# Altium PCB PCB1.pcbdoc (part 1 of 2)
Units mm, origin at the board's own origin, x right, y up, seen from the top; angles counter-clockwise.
Board outline 53.72 x 80.14 mm, 2 copper layers (Top Layer, Bottom Layer); 37 components, 55 nets, 218 pads, 259 vias.
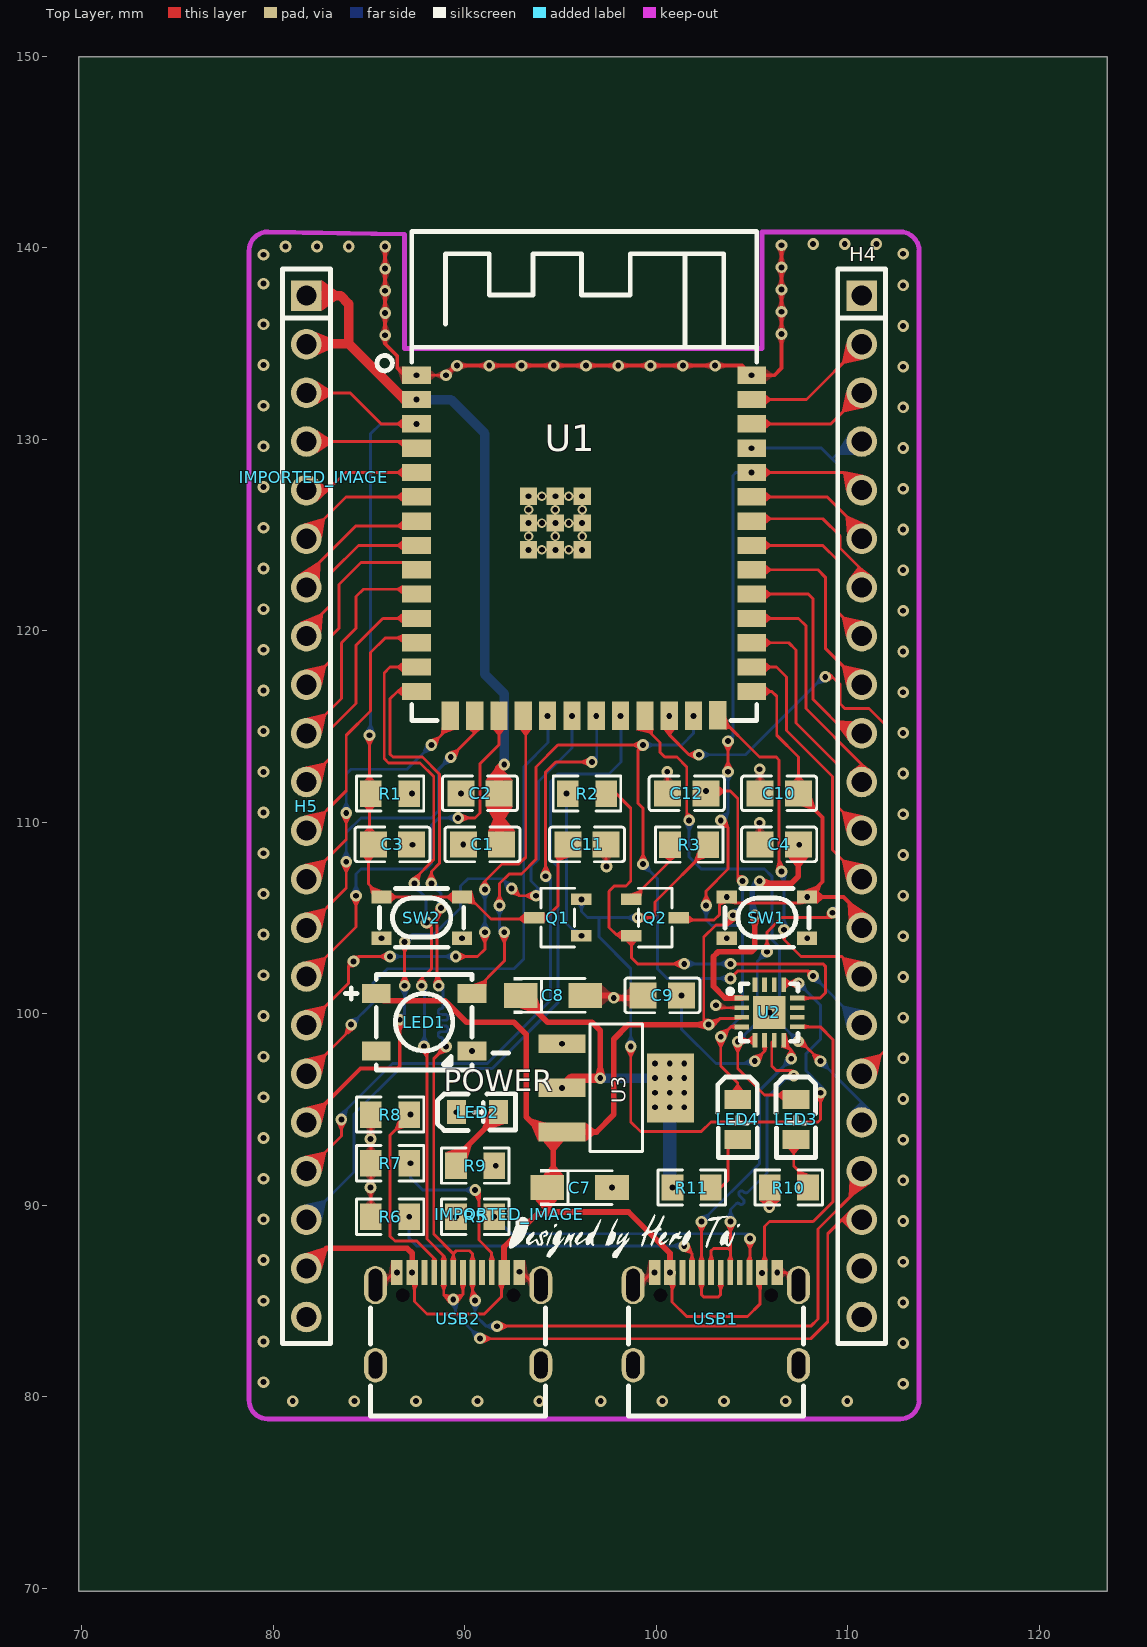
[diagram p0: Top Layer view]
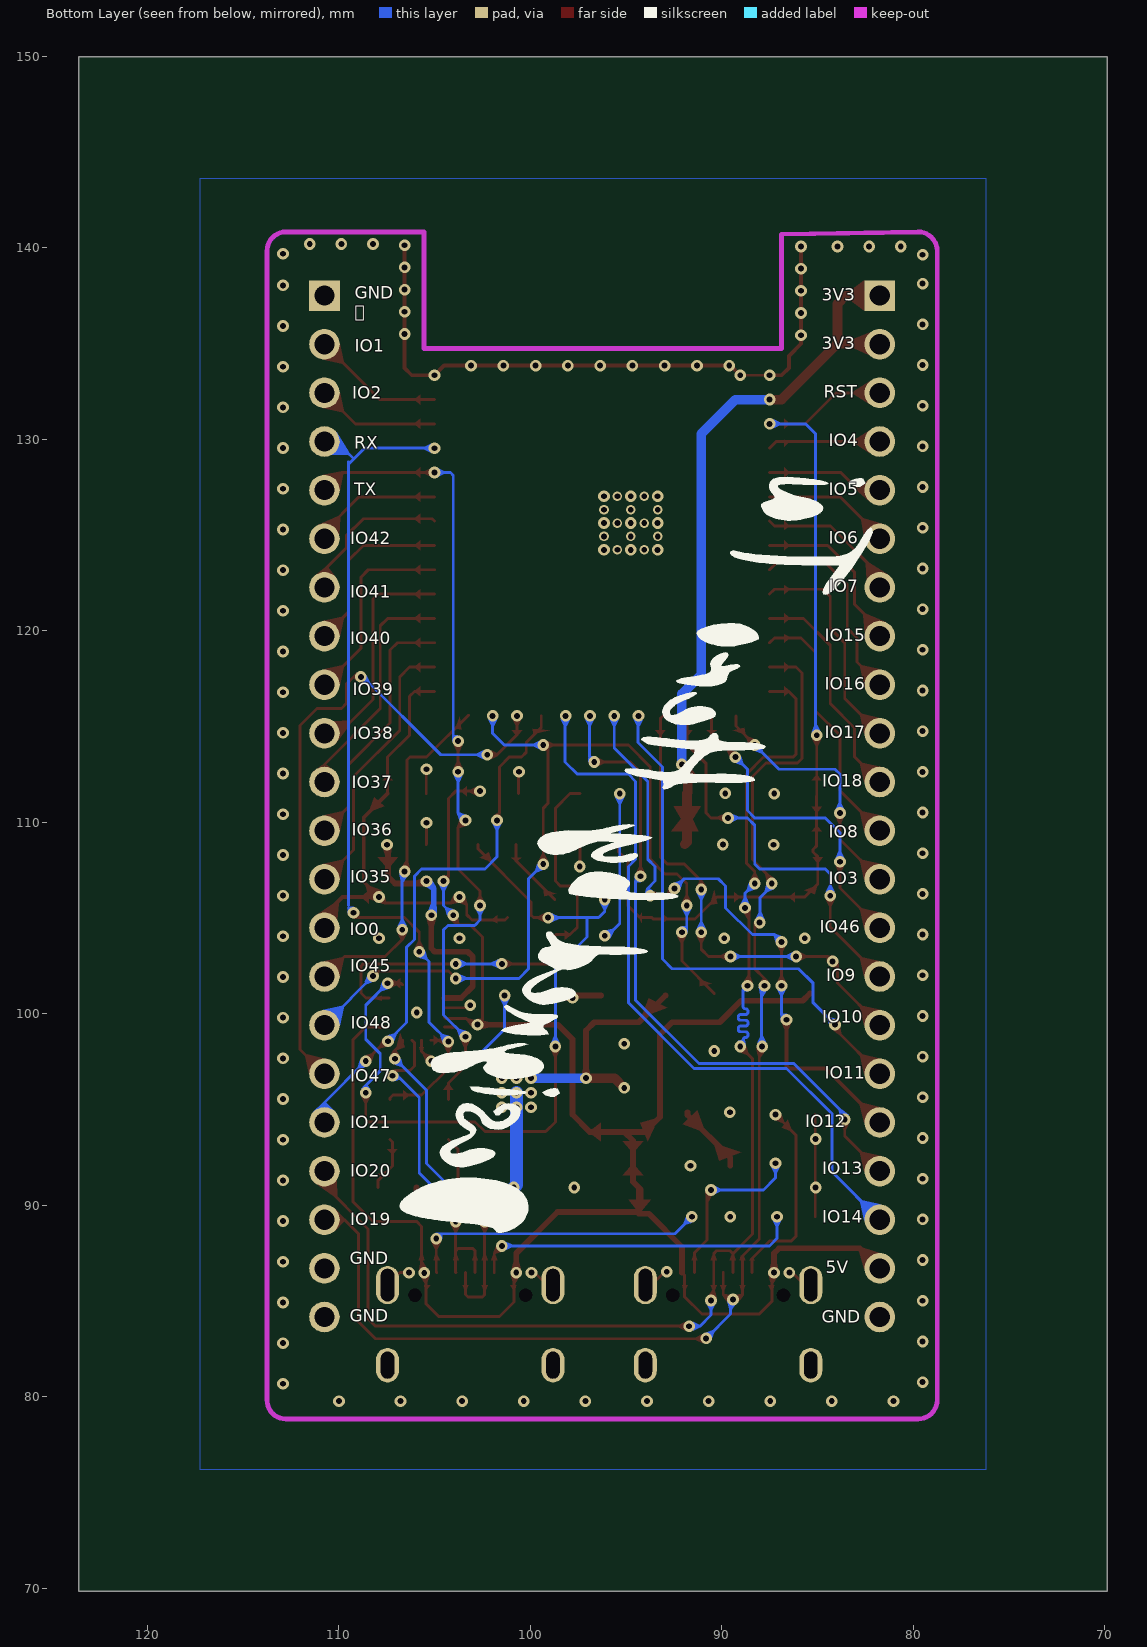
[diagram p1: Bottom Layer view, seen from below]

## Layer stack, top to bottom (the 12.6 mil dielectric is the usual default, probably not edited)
Top Layer: signal copper (thickness not stored)
Dielectric: dielectric 0.32, FR-4, Dk 4.8
Bottom Layer: signal copper (thickness not stored)

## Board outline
123.571,69.85 69.85,69.85 69.85,149.987 123.571,149.987

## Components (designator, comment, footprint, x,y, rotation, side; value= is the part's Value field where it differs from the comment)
C1 "0805B104K500NT" C0805 90.932,108.852 r0 top
C2 "CL21A106KOQNNNE" C0805 90.805,111.519 r0 top
C3 "CL21B105KBFNNNE" C0805 86.233,108.852 r180 top
C4 "CL21B105KBFNNNE" C0805 106.426,108.852 r180 top
C7 "TAJA106K016RNJ" CAP-SMD_L3.2-W1.6-RD-C7171 96.012,90.932 r0 top
C8 "TAJA106K016RNJ" CAP-SMD_L3.2-W1.6-RD-C7171 94.615,100.965 r0 top
C9 "0805B104K500NT" C0805 100.33,100.965 r0 top
C10 "0805B104K500NT" C0805 106.426,111.519 r0 top
C11 "0805B104K500NT" C0805 96.393,108.852 r180 top
C12 "CL21B105KBFNNNE" C0805 101.6,111.519 r0 top
H4 "X6511WV-22H-C30D60" HDR-TH_22P-P2.54-V-M 110.74,110.843 r270 top
H5 "X6511WV-22H-C30D60" HDR-TH_22P-P2.54-V-M 81.74,110.843 r270 top
IMPORTED_IMAGE "IMPORTED_IMAGE" IMPORTED_IMAGE 92.328,89.535 r0 top
IMPORTED_IMAGE "IMPORTED_IMAGE" IMPORTED_IMAGE 82.115,128.021 r0 top
LED1 "XL-5050RGBC-WS2812B" LED-SMD_4P-L5.0-W5.0-BL_XL-5050RGBC 87.884,99.568 r270 top
LED2 "NCD0805R1" LED0805-RD_RED 90.678,94.869 r0 top
LED3 "SZYY0805B" LED0805-R-RD_BLUE 107.315,94.488 r270 top
LED4 "SZYY0805B" LED0805-R-RD_BLUE 104.267,94.488 r270 top
Q1 "SS8050-G_C164886" SOT-23-3_L2.9-W1.6-P1.90-LS2.8-BR 94.869,105.029 r0 top
Q2 "SS8050-G_C164886" SOT-23-3_L2.9-W1.6-P1.90-LS2.8-BR 99.949,105.029 r180 top
R1 "0805W8F1002T5E_C17414" R0805 86.106,111.506 r0 top
R2 "0805W8F1002T5E_C17414" R0805 96.393,111.506 r0 top
R3 "0805W8F1002T5E_C17414" R0805 101.727,108.839 r0 top
R5 "0805W8F5101T5E" R0805 90.551,89.408 r0 top
R6 "0805W8F5101T5E" R0805 86.106,89.408 r0 top
R7 "0805W8F5101T5E" R0805 86.106,92.202 r0 top
R8 "0805W8F5101T5E" R0805 86.106,94.742 r0 top
R9 "RC0805FR-071KL" R0805 90.551,92.075 r180 top
R10 "RC0805FR-071KL" R0805 106.934,90.932 r180 top
R11 "RC0805FR-071KL" R0805 101.854,90.932 r180 top
SW1 "SKRPACE010" KEY-SMD_4P-L4.2-W3.2-P2.20-LS4.6 105.791,105.029 r0 top
SW2 "SKRPACE010" KEY-SMD_4P-L4.2-W3.2-P2.20-LS4.6 87.757,105.029 r0 top
U1 "ESP32-S3-WROOM-1-N16R8" WIRELM-SMD_ESP32-S3-WROOM-1 96.24,124.46 r0 top
U2 "CH343P" TQFN-16_L3.0-W3.0-P0.50-BL-EP1.7 105.918,100.076 r270 top
U3 "AMS1117-3.3_C347222" SOT-223-4_L6.5-W3.5-P2.30-LS7.0-BR 97.917,96.139 r180 top
USB1 "KH-TYPE-C-16P" USB-C-SMD_KH-TYPE-C-16P 103.124,84.074 r0 top
USB2 "KH-TYPE-C-16P" USB-C-SMD_KH-TYPE-C-16P 89.662,84.074 r0 top

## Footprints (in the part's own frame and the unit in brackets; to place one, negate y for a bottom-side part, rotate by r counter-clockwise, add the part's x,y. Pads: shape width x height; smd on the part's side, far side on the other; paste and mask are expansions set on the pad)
C0805 [mm]
  rect 1.41x1.35 smd paste-100 mask+0.051: 1(-1,0) 2(1,0)
  silkscreen extent -1.96,-0.9 1.96,0.9
CAP-SMD_L3.2-W1.6-RD-C7171 [mm]
  rect 1.758x1.296 smd paste+0 mask+0.051: 1(-1.686,0) 2(1.686,0)
  silkscreen extent -2.06,-0.95 1.68,0.95
HDR-TH_22P-P2.54-V-M [mm]
  rect 1.6x1.6 hole 1.05 paste+0 mask+0.051: 1(-26.67,0)
  round 1.6 hole 1.05 paste+0 mask+0.051: 2(-24.13,0) 3(-21.59,0) 4(-19.05,0) 5(-16.51,0) 6(-13.97,0) 7(-11.43,0) 8(-8.89,0) 9(-6.35,0) 10(-3.81,0) 11(-1.27,0) 12(1.27,0) 13(3.81,0) 14(6.35,0) 15(8.89,0) 16(11.43,0) 17(13.97,0) 18(16.51,0) 19(19.05,0) 20(21.59,0) 21(24.13,0) 22(26.67,0)
  silkscreen extent -28.06,-1.25 28.06,1.25
IMPORTED_IMAGE [mm]
  silkscreen extent 0,-2.29 12.07,0
KEY-SMD_4P-L4.2-W3.2-P2.20-LS4.6 [mm]
  rect 1.05x0.7 smd paste+0 mask+0.051: 1(-2.1,1.075) 2(2.1,1.075) 3(-2.1,-1.075) 4(2.1,-1.075)
  silkscreen extent -2.2,-1.55 2.2,1.52
LED0805-R-RD_BLUE [mm]
  rect 1x1.4 smd paste+0 mask+0.051: 1(1.05,0) 2(-1.05,0)
  silkscreen extent -2.22,-1.04 1.99,1.01
LED0805-RD_RED [mm]
  rect 1x1.25 smd paste+0 mask+0.051: 1(-1.1,0) 2(1.1,0)
  silkscreen extent -2.1,-0.95 1.98,0.96
LED-SMD_4P-L5.0-W5.0-BL_XL-5050RGBC [mm]
  rect 1x1.5 smd paste+0 mask+0.051: 1(-1.5,-2.5) 2(1.5,-2.5) 3(1.5,2.5) 4(-1.5,2.5)
  silkscreen extent -2.5,-4.1 2.5,4.4
R0805 [mm]
  rect 1.133x1.377 smd paste-100 mask+0.051: 1(-1,0) 2(1,0)
  silkscreen extent -1.76,-0.92 1.76,0.92
SOT-23-3_L2.9-W1.6-P1.90-LS2.8-BR [mm]
  rect 1.07x0.6 smd paste+0 mask+0.051: 1(1.235,-0.95) 2(1.235,0.95) 3(-1.235,0)
  silkscreen extent -0.88,-1.54 0.88,1.54
SOT-223-4_L6.5-W3.5-P2.30-LS7.0-BR [mm]
  rect 2.47x0.98 smd paste+0 mask+0.051: 1(2.835,-2.3) 2(2.835,0) 3(2.835,2.3)
  rect 2.47x3.6 smd paste+0 mask+0.051: 4(-2.835,0)
  silkscreen extent -1.37,-3.33 1.37,3.33
TQFN-16_L3.0-W3.0-P0.50-BL-EP1.7 [mm]
  rect 0.25x0.75 smd paste-100 mask+0.051: 1(-0.748,-1.45) 2(-0.249,-1.45) 3(0.252,-1.45) 4(0.751,-1.45) 9(0.75,1.45) 10(0.25,1.45) 11(-0.25,1.45) 12(-0.749,1.45)
  rect 0.75x0.25 smd paste-100 mask+0.051: 5(1.45,-0.75) 6(1.45,-0.25) 7(1.45,0.25) 8(1.45,0.75) 13(-1.45,0.75) 14(-1.45,0.25) 15(-1.45,-0.25) 16(-1.45,-0.75)
  rect 1.7x1.7 smd paste-100 mask+0.051: 17(0,0)
  silkscreen extent -1.5,-2.17 1.5,1.5
USB-C-SMD_KH-TYPE-C-16P [mm]
  oval 1.2x2 hole 0.7 slot 1.7 at 90 deg paste+0 mask+0.051: 1(-4.32,1.765) 2(4.32,1.765)
  oval 1.2x1.8 hole 0.7 slot 1.4 at 90 deg paste+0 mask+0.051: 3(-4.32,-2.415) 4(4.32,-2.415)
  rect 0.3x1.3 smd paste-100 mask+0.05: A1(-3.35,2.415) A4(-2.55,2.415) A5(-1.25,2.415) A6(-0.25,2.415) A7(0.25,2.415) A8(1.25,2.415) A9(2.55,2.415) A12(3.35,2.415) B1(3.05,2.415) B4(2.25,2.415) B5(1.75,2.415) B6(0.75,2.415) B7(-0.75,2.415) B8(-1.75,2.415) B9(-2.25,2.415) B12(-3.05,2.415)
  Multi-Layer board cut-out: -2.54,1.235 -2.575,1.387 -2.672,1.509 -2.812,1.576 -2.968,1.576 -3.108,1.509 -3.205,1.387 -3.24,1.235 -3.24,1.235 -3.205,1.083 -3.108,0.961 -2.968,0.894 -2.812,0.894 -2.672,0.961 -2.575,1.083 -2.54,1.235
  Multi-Layer board cut-out: 3.24,1.235 3.205,1.387 3.108,1.509 2.968,1.576 2.812,1.576 2.672,1.509 2.575,1.387 2.54,1.235 2.54,1.235 2.575,1.083 2.672,0.961 2.812,0.894 2.968,0.894 3.108,0.961 3.205,1.083 3.24,1.235
  silkscreen extent -4.57,-5.08 4.57,0.57
WIRELM-SMD_ESP32-S3-WROOM-1 [mm]
  rect 1.5x0.9 smd paste+0 mask+0.05: 1(-8.75,8.895) 2(-8.75,7.625) 3(-8.75,6.355) 4(-8.75,5.085) 5(-8.75,3.815) 6(-8.75,2.545) 7(-8.75,1.275) 8(-8.75,0.005) 9(-8.75,-1.265) 10(-8.75,-2.535) 11(-8.75,-3.805) 12(-8.75,-5.075) 13(-8.75,-6.345) 14(-8.75,-7.615) 27(8.75,-7.615) 28(8.75,-6.345) 29(8.75,-5.075) 30(8.75,-3.805) 31(8.75,-2.535) 32(8.75,-1.265) 33(8.75,0.005) 34(8.75,1.275) 35(8.75,2.545) 36(8.75,3.815) 37(8.75,5.085) 38(8.75,6.355) 39(8.75,7.625) 40(8.75,8.895)
  rect 0.9x1.5 smd paste+0 mask+0.05: 15(-6.985,-8.895) 16(-5.715,-8.895) 17(-4.445,-8.895) 18(-3.175,-8.895) 19(-1.905,-8.895) 20(-0.635,-8.895) 21(0.635,-8.895) 22(1.905,-8.895) 23(3.175,-8.895) 24(4.445,-8.895) 25(5.715,-8.895) 26(6.985,-8.865)
  rect 0.9x0.9 smd paste+0 mask+0.051: 41(-2.9,-0.225) 41(-2.9,1.175) 41(-2.9,2.575) 41(-1.5,-0.225) 41(-1.5,1.175) 41(-1.5,2.575) 41(-0.1,-0.225) 41(-0.1,1.175) 41(-0.1,2.575)
  silkscreen extent -10.81,-9.14 9.02,16.39

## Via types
v1: diameter 0.61, hole 0.305, Top Layer to Bottom Layer, 247 vias
v2: diameter 0.5, hole 0.3, Top Layer to Bottom Layer, 12 vias

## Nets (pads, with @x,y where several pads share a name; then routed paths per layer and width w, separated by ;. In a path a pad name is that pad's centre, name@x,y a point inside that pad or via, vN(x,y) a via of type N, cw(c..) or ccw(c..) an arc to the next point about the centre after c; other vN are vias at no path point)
3V3: C1.2 C2.2 C4.1 C8.1 H5.1 H5.2 R1.2 R9.1 R10.2 R11.2 U1.2 U2.1 U3.2 U3.4 | length 69.5
  Top Layer w0.3: C8.1@92.929,100.965 94.326,99.568 96.647,99.568 97.081,99.134 v1(97.081,96.647) ; U2.1@104.468,100.824 104.455,100.838 103.601,100.838 102.997,101.442 102.997,102.997 103.251,103.251 104.983,103.251 105.156,103.424 v1(105.156,105.156) ; v1(105.41,106.934) 105.537,106.807 107.061,106.807 107.426,107.172 C4.1@107.426,108.839 ; v1(105.918,89.916) 105.934,89.932 R10.2@105.934,90.932
  Top Layer w0.5: H5.2@81.74,134.973 81.768,135.001 83.947,135.001 ; H5.1@81.74,137.513 83.518,137.513 83.947,137.084 83.947,135.001 ; v1(87.49,132.085) 86.863,132.085 83.947,135.001 ; C1.2@91.932,108.852 91.805,108.979 C2.2@91.805,111.519 91.775,111.549 91.775,112.73 v1(92.075,113.03) ; v1(95.082,96.139) 95.59,96.647 v1(97.081,96.647)
  Bottom Layer w0.3: v1(105.156,105.156) 105.029,105.283 105.029,106.553 v1(105.41,106.934)
  Bottom Layer w0.5: v1(87.49,132.085) 89.281,132.085 91.059,130.307 91.059,117.729 92.075,116.713 v1(92.075,113.03) ; v1(97.081,96.647) v1(99.949,96.647)
  Bottom Layer w0.7: v1(100.711,95.885) v1(100.711,95.123) 100.711,91.075 v1(100.854,90.932)
  other v1: 91.624,92.075 99.949,95.123 101.473,95.123 99.949,95.885 101.473,95.885 100.711,96.647 101.473,96.647 99.949,97.409 100.711,97.409 101.473,97.409 107.474,108.832 87.249,111.506
5V_IN: C7.1 C12.2 H5.21 LED1.1 U2.3 U2.9 U3.3 USB1.A4 USB1.A9 USB1.B4 USB1.B9 USB2.A4 USB2.A9 USB2.B4 USB2.B9 | length 103.8
  Top Layer w0.15: v1(87.262,86.489) 87.376,86.375 87.376,84.986 88.034,84.328 91.03,84.328 91.935,85.233 91.935,86.362 USB2.A9@92.062,86.489 ; v1(100.724,86.489) 100.838,86.375 100.838,84.963 101.6,84.201 104.775,84.201 105.437,84.863 105.437,86.426 USB1.B4@105.374,86.489 ; v1(102.616,111.633) 103.886,111.633 104.267,111.252 104.267,107.188 v1(104.521,106.934) ; v1(104.013,105.156) 104.013,104.902 103.759,104.648 103.124,104.648 102.489,104.013 102.489,99.695 v1(102.743,99.441) 103.011,99.441 103.321,99.752 104.395,99.752 U2.3@104.468,99.824 ; v1(105.524,86.477) 105.664,86.617 105.664,88.9 105.918,89.154 108.204,89.154 109.244,90.194 109.244,98.655 108.573,99.326 U2.9@107.368,99.326
  Top Layer w0.3: H5.21@81.74,86.713 82.784,87.757 87.008,87.757 87.262,87.503 v1(87.262,86.489) ; LED1.1@85.384,101.068 85.765,100.687 88.981,100.687 90.1,99.568 92.583,99.568 93.218,98.933 93.218,94.615 93.994,93.839 U3.3@95.082,93.839 ; USB2.A9@92.062,86.489 92.062,87.828 93.804,89.57 94.326,89.57 ; v1(100.724,86.489) 100.724,87.503 98.565,89.662 94.417,89.662 94.326,89.57 ; v1@102.743,99.554 v1(102.743,99.441) 98.552,99.441 97.79,98.679 97.79,94.742 96.887,93.839 U3.3@95.082,93.839 ; 94.326,89.57 94.326,89.754 ; 94.326,89.754 94.217,89.862 94.217,90.823 C7.1@94.326,90.932 ; 94.326,89.754 C7.1@94.326,90.932 ; C7.1@94.326,90.932 94.626,91.232 94.626,93.383 U3.3@95.082,93.839
  Bottom Layer w0.15: v1(104.013,105.156) 104.521,105.664 v1(104.521,106.934)
$1N2056: Q1.1 R2.1 | length 7.8
  Bottom Layer w0.15: v1(95.32,111.506) 95.32,104.721 95.962,104.079 v1(96.104,104.079)
$1N2059: Q2.1 R3.1 | length 3.7
  Top Layer w0.15: Q2.1@98.714,105.979 100.727,107.992 R3.1@100.727,108.839
$1N2366: R5.2 USB1.B5 | length 15.6
  Top Layer w0.15: USB1.B5@104.874,86.489 104.902,86.517 v1(104.902,88.265)
  Bottom Layer w0.15: v1(91.551,89.408) 92.44,88.519 104.648,88.519 v1(104.902,88.265)
$1N2384: R6.2 USB1.A5 | length 17.2
  Top Layer w0.15: v1(101.473,87.884) 101.874,87.483 USB1.A5@101.874,86.489
  Bottom Layer w0.15: v1(87.106,89.408) 87.106,88.281 87.503,87.884 v1(101.473,87.884)
$1N3062: C9.2 U2.6 | length 7.7
  Top Layer w0.15: v1(105.156,97.536) 105.668,98.048 U2.6@105.668,98.626
  Bottom Layer w0.15: v1(101.33,100.965) 101.33,99.203 103.124,97.409 105.029,97.409 v1(105.156,97.536)
$1N3525: R7.2 USB2.B5 | length 9.1
  Top Layer w0.15: v1(90.551,90.805) 90.758,90.598 90.758,88.185 91.412,87.531 USB2.B5@91.412,86.489
  Bottom Layer w0.15: v1(87.181,92.202) 87.181,91.44 87.816,90.805 v1(90.551,90.805)
$1N3528: R8.2 USB2.A5 | length 10.3
  Top Layer w0.15: v1(87.181,94.742) 86.106,93.667 86.106,88.392 86.36,88.138 87.503,88.138 88.412,87.229 USB2.A5@88.412,86.489
$1N5776: LED2.2 R9.2 | length 3.7
  Top Layer w0.3: R9.2@89.551,92.075 89.551,92.499 91.778,94.726 LED2.2@91.778,94.869
$1N6033: LED3.1 R10.1 | length 2.9
  Top Layer w0.15: LED3.1@107.315,93.438 107.188,93.311 107.188,92.059 107.934,91.313 R10.1@107.934,90.932
$1N6044: LED4.1 R11.1 | length 3.4
  Top Layer w0.15: R11.1@102.854,90.932 103.378,90.932 103.759,91.313 103.759,92.93 LED4.1@104.267,93.438
CH_RX: H4.4 LED3.2 U1.37 U2.5 | length 46.5
  Top Layer w0.15: U2.5@105.168,98.626 104.406,98.626 104.267,98.487 104.267,97.155 105.664,95.758 107.165,95.758 107.315,95.608 LED3.2@107.315,95.538 ; v1(105.791,103.251) 105.791,104.267 106.553,105.029 108.966,105.029 v1(109.22,105.283)
  Bottom Layer w0.15: v1(104.267,98.552) 105.283,99.568 105.283,102.743 v1(105.791,103.251) ; v1(104.99,129.545) 108.641,129.545 109.22,128.966 ; v1(109.22,105.283) 109.474,105.537 ; 109.474,105.664 109.474,128.712 ; 109.474,128.839 109.474,128.712 ; H4.4@110.74,129.893 110.105,129.893 109.22,129.008 109.22,128.966 ; 109.22,128.966 109.474,128.712
CH_TX: H4.5 LED4.2 U1.36 U2.4 | length 44.4
  Top Layer w0.15: v1(102.616,105.664) 102.616,106.426 103.759,107.569 103.759,109.728 v1(103.378,110.109) ; v1(103.759,112.649) v1(103.759,114.246) ; LED4.2@104.267,95.538 104.267,96.393 103.378,97.282 v1(103.378,98.806) 103.897,99.325 U2.4@104.468,99.325 ; v1(104.99,128.275) 109.818,128.275 H4.5@110.74,127.353
  Bottom Layer w0.15: v1(102.616,105.664) 102.616,104.902 102.894,104.624 104.291,104.624 104.521,104.394 104.521,99.949 v1(103.378,98.806) ; v1(103.378,110.109) 103.759,110.49 v1(103.759,112.649) ; v1(103.759,114.246) 104.013,114.5 104.013,128.125 104.163,128.275 v1(104.99,128.275)
CH_USB+: U2.7 USB1.A6 USB1.B6 | length 17.7
  Top Layer w0.15: USB1.A6@102.874,86.489 102.874,87.634 102.997,87.757 103.759,87.757 103.886,87.63 ; USB1.B6@103.874,86.489 103.886,86.501 103.886,87.63 ; v1(103.886,89.154) 103.886,87.63 ; U2.7@106.168,98.626 106.041,98.499 106.041,97.286 106.276,97.051 107.038,97.051 107.188,96.901 v1(107.188,96.774)
  Bottom Layer w0.15: v1(103.886,89.154) 103.886,89.789 104.178,90.081 cw(c104.268,89.991) 104.358,90.081 ccw(c104.447,90.171) 104.537,90.081 104.57,90.113 ccw(c104.48,90.203) 104.57,90.293 104.361,90.501 cw(c104.467,90.608) 104.573,90.714 104.586,90.701 ccw(c104.692,90.807) 104.798,90.701 105.791,91.694 105.791,95.631 106.807,96.647 107.061,96.647 v1(107.188,96.774)
CH_USB-: U2.8 USB1.A7 USB1.B7 | length 17.6
  Top Layer w0.15: v1(102.374,89.154) USB1.B7@102.374,86.489 102.374,85.332 102.489,85.217 103.251,85.217 103.374,85.34 USB1.A7@103.374,86.489 ; U2.8@106.668,98.626 106.668,98.499 107.061,98.106 v1(107.061,97.663)
  Bottom Layer w0.15: v1(102.374,89.154) 105.41,92.19 105.41,96.012 v1(107.061,97.663)
CHIP_UP: C3.2 C11.2 H5.3 Q1.3 R1.1 SW2.1 SW2.2 U1.3 | length 47.1
  Top Layer w0.14: R1.1@85.033,111.379 v1(85.033,114.554)
  Top Layer w0.15: H5.3@81.74,132.433 84.026,132.433 85.644,130.815 v1(87.49,130.815) ; R1.1@85.033,111.379 85.033,108.785 85.233,108.585 85.233,108.458 84.979,108.204 84.979,106.782 SW2.1@85.657,106.104 SW2.2@89.857,106.104 90.238,106.104 91.381,104.961 93.566,104.961 Q1.3@93.634,105.029 94.269,105.029 94.885,105.645 94.885,107.966 95.393,108.474 C11.2@95.393,108.852
  Bottom Layer w0.15: v1(85.033,114.554) 85.09,114.611 85.09,130.302 85.603,130.815 v1(87.49,130.815)
DTR: Q2.2 R2.2 U2.12 | length 24.4
  Top Layer w0.15: R2.2@97.393,111.506 97.917,111.506 98.679,110.744 98.679,106.934 98.425,106.68 97.813,106.68 97.536,106.403 97.536,104.521 97.917,104.14 98.653,104.14 Q2.2@98.714,104.079 98.714,102.936 99.034,102.616 v1(101.473,102.616) ; v1(103.886,102.616) 108.712,102.616 108.839,102.489 108.839,101.092 108.572,100.825 U2.12@107.368,100.825
  Bottom Layer w0.15: v1(101.473,102.616) v1(103.886,102.616)
GND: C1.1 C2.1 C3.1 C4.2 C7.2 C8.2 C9.1 C10.1 C11.1 C12.1 H4.1 H4.21 H4.22 H5.22 LED1.3 LED2.1 R5.1 R6.1 R7.1 R8.1 SW1.3 SW1.4 SW2.3 SW2.4 U1.1 U1.40 U1.41 U2.2 U2.17 U3.1 USB1.1 USB1.2 USB1.3 USB1.4 USB1.A1 USB1.A12 USB1.B1 USB1.B12 USB2.1 USB2.2 USB2.3 USB2.4 USB2.A1 USB2.A12 USB2.B1 USB2.B12 | length 53.4
  Top Layer w0.15: R6.1@85.106,89.408 85.106,90.916 v1(85.09,90.932) 85.106,90.948 R7.1@85.106,92.202 85.106,93.456 v1(85.09,93.472) 85.106,93.488 R8.1@85.106,94.742 ; USB2.1@85.342,85.839 85.662,85.839 USB2.A1@86.312,86.489 ; v1(87.49,133.355) 89.022,133.355 v1(89.027,133.35) ; USB2.A12@93.012,86.489 93.662,85.839 USB2.2@93.982,85.839 ; C11.1@97.393,108.852 97.393,107.712 v1(97.409,107.696) ; USB1.1@98.804,85.839 99.124,85.839 USB1.A1@99.774,86.489 ; v1(100.584,112.649) 100.6,112.633 C12.1@100.6,111.519 ; v1(103.124,100.457) 103.256,100.325 U2.2@104.468,100.325 ; v1(105.41,109.982) 105.41,108.868 C4.2@105.426,108.852 ; v1(105.41,112.776) 105.426,112.76 C10.1@105.426,111.519 ; USB1.A12@106.474,86.489 106.794,86.489 USB1.2@107.444,85.839
  Top Layer w0.2: v1(85.852,140.081) v1(85.852,138.922) v1(85.852,137.763) v1(85.852,136.604) v1(85.852,135.445) 85.852,135.001 86.487,134.366 86.487,133.731 86.863,133.355 v1(87.49,133.355) ; v1(89.027,133.35) 89.535,133.858 v1(89.603,133.858) v1(91.288,133.858) v1(92.973,133.858) v1(94.658,133.858) v1(96.343,133.858) v1(98.028,133.858) v1(99.713,133.858) v1(101.398,133.858) v1(103.083,133.858) 104.487,133.858 v1(104.99,133.355) 106.177,133.355 106.553,133.731 v1(106.553,135.509) v1(106.553,136.668) v1(106.553,137.827) v1(106.553,138.986) v1(106.553,140.145)
  Top Layer w0.3: C8.2@96.301,100.965 97.663,100.965 v1(97.79,100.838) 99.203,100.838 C9.1@99.33,100.965
  other v1: 81.026,79.78 84.243,79.78 87.461,79.78 90.678,79.78 93.895,79.78 97.113,79.78 100.33,79.78 103.547,79.78 106.765,79.78 109.982,79.78 112.903,80.683 79.502,80.772 112.903,82.808 79.502,82.897 112.903,84.933 79.502,85.021 86.462,86.489 99.924,86.489 106.324,86.489 92.862,86.535 112.903,87.057 79.502,87.146 112.903,89.182 79.502,89.271 89.551,89.408 97.698,90.932 112.903,91.307 79.502,91.395 112.903,93.431 79.502,93.52 89.569,94.869 112.903,95.556 79.502,95.645 112.903,97.681 79.502,97.769 90.384,98.068 95.082,98.439 112.903,99.805 79.502,99.894 105.918,100.076 112.903,101.93 79.502,102.018 85.657,103.954 89.857,103.954 103.691,103.954 107.891,103.954 112.903,104.055 79.502,104.143 112.903,106.179 79.502,106.268 112.903,108.304 79.502,108.392 87.281,108.832 89.932,108.852 112.903,110.429 79.502,110.517 89.805,111.519 112.903,112.553 79.502,112.642 112.903,114.678 79.502,114.766 112.903,116.803 79.502,116.891 112.903,118.927 79.502,119.016 112.903,121.052 79.502,121.14 112.903,123.176 79.502,123.265 93.34,124.235 94.74,124.235 96.14,124.235 112.903,125.301 79.502,125.39 93.34,125.635 94.74,125.635 96.14,125.635 93.34,127.035 94.74,127.035 96.14,127.035 112.903,127.426 79.502,127.514 112.903,129.55 79.502,129.639 112.903,131.675 79.502,131.764 112.903,133.8 79.502,133.888 112.903,135.924 79.502,136.013 112.903,138.049 79.502,138.138 79.502,139.643 112.903,139.7 80.645,140.081 82.296,140.081 83.947,140.081 108.204,140.208 109.855,140.208 111.506,140.208
GPIO0: C10.2 H4.14 Q2.3 SW1.1 SW1.2 U1.27 | length 25
  Top Layer w0.15: Q2.3@101.184,105.029 101.311,104.902 103.033,104.902 103.31,105.179 103.31,105.723 v1(103.691,106.104) 103.818,106.104 104.133,105.789 107.576,105.789 v1(107.891,106.104) ; U1.27@104.99,116.845 104.995,116.84 106.045,116.84 106.299,116.586 106.299,114.554 107.442,113.411 C10.2@107.442,111.506
  Top Layer w0.2: C10.2@107.442,111.506 108.689,110.259 108.689,106.902 v1(107.891,106.104) 109.796,106.104 110.74,105.16 H4.14@110.74,104.493
GPIO1: H4.2 U1.39 | length 6.9
  Top Layer w0.15: U1.39@104.99,132.085 107.852,132.085 H4.2@110.74,134.973
GPIO2: H4.3 U1.38 | length 6.4
  Top Layer w0.15: U1.38@104.99,130.815 109.122,130.815 H4.3@110.74,132.433
GPIO3: H5.13 U1.15 | length 13.4
  Top Layer w0.15: H5.13@81.74,107.033 83.82,109.113 v1(83.82,110.49) ; v1(88.265,114.046) 89.255,115.036 U1.15@89.255,115.565
  Bottom Layer w0.15: v1(83.82,110.49) 83.82,112.522 84.074,112.776 86.995,112.776 v1(88.265,114.046)
GPIO4: H5.4 U1.4 | length 5.9
  Top Layer w0.15: H5.4@81.74,129.893 87.142,129.893 U1.4@87.49,129.545
GPIO5: H5.5 U1.5 | length 6.1
  Top Layer w0.15: H5.5@81.74,127.353 82.854,127.353 83.776,128.275 U1.5@87.49,128.275
GPIO6: H5.6 U1.6 | length 6.7
  Top Layer w0.15: H5.6@81.74,124.813 81.74,124.94 83.8,127 87.485,127 U1.6@87.49,127.005
GPIO7: H5.7 U1.7 | length 7.6
  Top Layer w0.15: H5.7@81.74,122.273 81.74,122.908 84.313,125.481 87.236,125.481 U1.7@87.49,125.735
GPIO8: H5.12 U1.12 | length 13.5
  Top Layer w0.15: H5.12@81.74,109.573 83.82,111.653 83.82,114.554 85.09,115.824 85.09,118.872 85.857,119.639 87.236,119.639 U1.12@87.49,119.385
GPIO9: H5.15 U1.17 | length 20.9
  Top Layer w0.15: H5.15@81.74,101.953 84.328,104.541 v1(84.328,106.172) ; v1(89.662,110.236) 90.551,110.236 90.805,110.49 90.805,113.065 91.795,114.055 U1.17@91.795,115.565
  Bottom Layer w0.15: v1(84.328,106.172) 84.328,107.315 84.582,107.569 88.011,107.569 88.265,107.823 88.265,109.855 88.646,110.236 v1(89.662,110.236)
GPIO10: H5.16 U1.18 | length 25.1
  Top Layer w0.15: H5.16@81.74,99.413 83.947,101.62 83.947,102.489 v1(84.201,102.743) 84.455,102.997 v1(86.106,102.997) ; v1(89.535,102.997) 90.678,102.997 91.059,103.378 v1(91.059,104.267) ; v1(91.059,106.498) 91.059,106.934 91.948,107.823 92.837,107.823 93.192,108.178 93.192,115.438 U1.18@93.065,115.565
  Bottom Layer w0.15: v1(86.106,102.997) v1(89.535,102.997) ; v1(91.059,104.267) v1(91.059,106.498)
GPIO11: H5.17 U1.19 | length 27.8
  Top Layer w0.15: H5.17@81.74,96.873 84.074,99.207 v1(84.074,99.441)
  Bottom Layer w0.15: v1(84.074,99.441) 85.217,100.584 85.217,101.6 85.979,102.362 92.583,102.362 93.091,102.87 93.091,112.903 94.361,114.173 94.361,115.539 v1(94.335,115.565)
GPIO12: H5.18 U1.20 | length 32.4
  Top Layer w0.15: v1(86.868,101.473) v1(86.868,103.759) ; v1(92.456,106.553) 92.837,106.172 v1(93.726,106.172)
  Top Layer w0.2: H5.18@81.74,94.333 84.562,97.155 86.487,97.155 86.614,97.282 v1(86.614,99.695)
  Bottom Layer w0.15: v1(86.614,99.695) 86.868,99.949 v1(86.868,101.473) ; v1(86.868,103.759) 87.249,104.14 88.392,104.14 89.789,105.537 89.789,106.68 90.17,107.061 91.948,107.061 v1(92.456,106.553) ; v1(93.726,106.172) 93.853,106.299 93.853,106.553 93.472,106.934 93.472,107.696 93.853,108.077 93.853,112.141 95.605,113.893 v1(95.605,115.565)
GPIO13: H5.19 U1.21 | length 34.3
  Top Layer w0.15: H5.19@81.74,91.793 83.566,93.619 v1(83.566,94.488) ; v1(94.234,107.188) 94.234,112.626 94.765,113.157 v1(96.647,113.157)
  Bottom Layer w0.15: v1(83.566,94.488) 83.566,94.742 86.233,97.409 91.186,97.409 94.488,100.711 94.488,106.934 v1(94.234,107.188) ; v1(96.647,113.157) 96.901,113.411 96.901,115.539 v1(96.875,115.565)
GPIO14: H5.20 U1.22 | length 37.8
  Bottom Layer w0.15: H5.20@81.74,89.253 84.225,91.738 84.225,94.766 86.614,97.155 91.44,97.155 94.869,100.584 94.869,107.696 94.488,108.077 94.488,112.141 94.869,112.522 97.536,112.522 98.171,113.157 98.171,115.539 v1(98.145,115.565)
GPIO15: H5.8 U1.8 | length 8.9
  Top Layer w0.15: H5.8@81.74,119.733 81.74,120.072 83.058,121.39 83.058,123.063 84.46,124.465 U1.8@87.49,124.465
GPIO16: H5.9 U1.9 | length 10.6
  Top Layer w0.15: H5.9@81.74,117.193 82.931,118.384 82.931,119.634 83.439,120.142 83.439,122.428 84.587,123.576 87.109,123.576 U1.9@87.49,123.195
GPIO17: H5.10 U1.10 | length 11.6
  Top Layer w0.15: H5.10@81.74,114.653 83.566,116.479 83.566,119.38 84.328,120.142 84.328,121.793 84.714,122.179 87.236,122.179 U1.10@87.49,121.925
GPIO18: H5.11 U1.11 | length 12
  Top Layer w0.15: H5.11@81.74,112.113 83.058,113.431 83.058,114.935 84.328,116.205 84.328,119.253 85.73,120.655 U1.11@87.49,120.655
GPIO19: H4.20 U1.13 USB2.A7 USB2.B7 | length 68
  Top Layer w0.15: v1(87.376,106.807) 87.376,107.04 88.392,108.056 88.392,112.395 87.678,113.109 86.027,113.109 85.804,113.332 85.804,117.808 86.111,118.115 U1.13@87.49,118.115 ; v1(87.757,101.473) 87.757,101.854 88.265,102.362 88.265,104.521 v1(88.011,104.775) ; v1(87.884,98.298) 88.034,98.148 88.034,88.242 88.912,87.364 USB2.B7@88.912,86.489 88.912,85.332 89.154,85.09 v1(89.408,85.09) 89.662,85.09 89.912,85.34 USB2.A7@89.912,86.489 ; v1(90.805,83.058) 90.829,83.034 108.077,83.034 108.966,83.923 108.966,88.519 109.7,89.253 H4.20@110.74,89.253
  Bottom Layer w0.15: v1(87.376,106.807) 87.376,106.68 87.987,106.069 v1@87.987,104.799 ; v1(87.757,101.473) 87.907,101.323 87.907,98.321 v1(87.884,98.298) ; v1(89.408,85.09) 89.535,84.963 89.535,84.328 v1(90.805,83.058)
GPIO20: H4.19 U1.14 USB2.A6 USB2.B6 | length 68.1
  Top Layer w0.15: U1.14@87.49,116.845 86.492,116.845 86.106,116.459 86.106,113.561 86.256,113.411 87.804,113.411 88.694,112.52 88.694,107.871 88.265,107.442 v1(88.265,106.807) ; v1(88.646,101.473) 88.567,101.552 88.567,105.331 v1(88.773,105.537) ; v1(89.027,98.298) 88.392,97.663 88.392,88.5 89.412,87.48 ; USB2.A6@89.412,86.489 89.412,87.48 ; v1(90.551,85.031) 90.412,85.17 USB2.B6@90.412,86.489 90.412,87.48 90.262,87.63 89.562,87.63 89.412,87.48 ; v1(91.694,83.693) 108.077,83.693 108.458,84.074 108.458,88.773 110.74,91.055 H4.19@110.74,91.793
  Bottom Layer w0.15: v1(88.265,106.807) 88.773,106.299 v1(88.773,105.537) ; v1(88.646,101.473) 88.877,101.242 88.877,100.394 cw(c88.75,100.394) 88.75,100.267 ccw(c88.75,100.14) 88.623,100.14 88.623,100.094 ccw(c88.75,100.094) 88.75,99.967 89.004,99.967 cw(c89.004,99.84) 89.131,99.84 89.131,99.794 cw(c89.004,99.794) 89.004,99.667 88.75,99.667 ccw(c88.75,99.54) 88.623,99.54 88.623,99.494 ccw(c88.75,99.494) 88.75,99.367 89.004,99.367 cw(c89.004,99.24) 89.131,99.24 89.131,99.194 cw(c89.004,99.194) 89.004,99.067 88.75,99.067 ccw(c88.75,98.94) 88.623,98.94 88.623,98.894 ccw(c88.75,98.894) 88.75,98.767 cw(c88.75,98.64) 88.877,98.64 88.877,98.448 v1(89.027,98.298) ; v1(90.551,85.031) 90.551,84.269 91.127,83.693 v1(91.694,83.693)
GPIO21: H4.18 U1.23 | length 28.3
  Top Layer w0.15: U1.23@99.415,115.565 99.415,114.961 100.203,114.173 100.203,113.665 100.457,113.411 101.092,113.411 101.6,112.903 101.6,110.49 101.727,110.363 v1(101.727,110.109) ; v1(107.418,98.576) 107.545,98.576 v1(108.585,97.536)
  Bottom Layer w0.15: v1(101.727,110.109) 101.727,108.204 102.362,107.569 105.664,107.569 106.045,107.188 106.045,103.886 106.45,103.481 106.45,99.544 v1(107.418,98.576) ; v1(108.585,97.536) 110.74,95.381 H4.18@110.74,94.333
GPIO35: H4.13 U1.28 | length 14.2
  Top Layer w0.15: U1.28@104.99,118.115 106.294,118.115 106.807,117.602 106.807,114.808 109.22,112.395 109.22,108.553 H4.13@110.74,107.033
GPIO36: H4.12 U1.29 | length 13.3
  Top Layer w0.15: U1.29@104.99,119.385 106.929,119.385 107.315,118.999 107.315,115.189 109.474,113.03 109.474,110.839 H4.12@110.74,109.573
GPIO37: H4.11 U1.30 | length 12.4
  Top Layer w0.15: U1.30@104.99,120.655 107.437,120.655 107.823,120.269 107.823,115.951 110.74,113.034 H4.11@110.74,112.113
GPIO38: H4.10 U1.31 | length 11.8
  Top Layer w0.15: U1.31@104.99,121.925 107.945,121.925 108.204,121.666 108.204,116.427 109.978,114.653 H4.10@110.74,114.653
GPIO39: H4.9 U1.32 | length 10.4
  Top Layer w0.15: U1.32@104.99,123.195 108.453,123.195 108.839,122.809 108.839,119.094 H4.9@110.74,117.193
GPIO40: H4.8 U1.33 | length 9.3
  Top Layer w0.15: U1.33@104.99,124.465 108.707,124.465 109.474,123.698 109.474,120.999 H4.8@110.74,119.733
GPIO41: H4.7 U1.34 | length 8.2
  Top Layer w0.15: U1.34@104.99,125.735 105.117,125.862 108.707,125.862 109.601,124.968 109.601,124.333 110.617,123.317 110.617,122.396 H4.7@110.74,122.273
GPIO42: H4.6 U1.35 | length 6.9
  Top Layer w0.15: U1.35@104.99,127.005 108.929,127.005 110.74,125.194 H4.6@110.74,124.813
GPIO45: H4.15 U1.26 | length 18.5
  Top Layer w0.15: U1.26@103.225,115.595 105.409,113.411 106.276,113.411 106.426,113.261 106.426,107.569 v1(106.553,107.442) ; v1(106.68,104.394) 106.68,103.886 107.569,102.997 109.696,102.997 H4.15@110.74,101.953
  Bottom Layer w0.15: v1(106.553,107.442) 106.68,107.315 v1(106.68,104.394)
GPIO46: H5.14 U1.16 | length 16.9
  Top Layer w0.15: H5.14@81.74,104.493 83.82,106.573 v1(83.82,107.95) ; v1(89.281,113.411) 90.525,114.655 U1.16@90.525,115.565
  Bottom Layer w0.15: v1(83.82,107.95) 83.82,109.474 84.582,110.236 88.265,110.236 88.646,110.617 88.646,112.776 v1(89.281,113.411)
GPIO47: H4.17 U1.24 | length 34.8
  Top Layer w0.15: v1(100.685,115.565) 100.685,114.58 101.727,113.538 v1(102.235,113.538) ; v1(108.839,117.602) 109.22,117.602 109.601,117.221 109.601,116.205 109.855,115.951 111.125,115.951 112.014,115.062 112.014,98.147 H4.17@110.74,96.873
  Bottom Layer w0.15: v1(102.235,113.538) 104.67,113.538 108.734,117.602 v1(108.839,117.602)
GPIO48: H4.16 LED1.4 U1.25 | length 48.1
  Top Layer w0.15: LED1.4@90.384,101.068 92.075,102.759 v1(92.075,104.267) ; v1(91.821,105.664) 91.821,106.807 92.329,107.315 92.964,107.315 93.726,108.077 93.726,112.903 94.869,114.046 v1(99.314,114.046) 99.06,113.792 99.06,110.998 99.314,110.744 v1(99.314,107.823) ; v1(103.886,101.854) 104.267,102.235 107.95,102.235 v1(108.204,101.981)
  Bottom Layer w0.15: v1(91.821,105.664) 91.821,104.521 v1(92.075,104.267) ; v1(99.314,107.823) 100.076,107.061 100.076,102.362 100.584,101.854 v1(103.886,101.854) ; v1(99.314,114.046) 101.346,114.046 101.955,114.655 v1(101.955,115.565) ; v1(108.204,101.981) 109.347,100.838 109.347,100.806 H4.16@110.74,99.413
RTS: Q1.2 R3.2 U2.13 | length 40.3
  Top Layer w0.15: v1(98.679,98.298) 98.679,94.361 99.187,93.853 102.362,93.853 102.87,94.361 108.458,94.361 108.585,94.488 v1(108.585,95.885) ; v1(99.06,105.029) 99.822,105.029 99.949,105.156 99.949,105.849 102.727,108.627 R3.2@102.727,108.839 ; U2.13@106.668,101.526 106.742,101.6 v1(107.442,101.6)
  Bottom Layer w0.15: v1(96.104,105.979) 96.104,105.344 96.419,105.029 97.025,105.029 ; v1(98.679,98.298) 98.679,102.362 97.028,104.013 97.028,105.026 97.025,105.029 ; v1(99.06,105.029) 97.025,105.029 ; v1(107.442,101.6) 108.585,100.457 108.585,98.679 107.823,97.917 107.823,97.028 108.585,96.266 v1(108.585,95.885)
"": LED1.2 U2.10 U2.11 U2.14 U2.15 U2.16 USB1.A8 USB1.B8 USB2.A8 USB2.B8
  other v2: 94.04,124.235 95.44,124.235 93.34,124.935 94.74,124.935 96.14,124.935 94.04,125.635 95.44,125.635 93.34,126.335 94.74,126.335 96.14,126.335 94.04,127.035 95.44,127.035

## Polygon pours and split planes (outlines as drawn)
GND on Top Layer (solid, remove dead copper, pour order 0): 77.343,77.597 115.443,77.597 115.443,142.621 77.343,142.621
GND on Bottom Layer (solid, remove dead copper, pour order 1): 76.2,76.2 117.221,76.2 117.221,143.637 76.2,143.637
GND on GND (split plane): 79.74,79.1 cw(c79.368,79.471) 78.997,79.843 78.997,139.843 cw(c79.373,140.209) 79.738,140.586 86.611,140.464 86.611,134.747 ccw(c86.74,134.619) 86.868,134.49 105.537,134.49 ccw(c105.665,134.619) 105.794,134.747 105.794,140.586 112.74,140.586 cw(c113.112,140.215) 113.483,139.843 113.483,79.843 cw(c113.112,79.471) 112.74,79.1 79.74,79.1
GND on GND (split plane): 97.945,85.966 98.804,85.966 98.804,85.712 97.945,85.712
GND on GND (split plane): 98.804,85.966 99.663,85.966 99.663,85.712 98.804,85.712
GND on GND (split plane): 98.677,85.839 98.677,87.098 98.931,87.098 98.931,85.839
GND on GND (split plane): 98.931,85.839 98.931,84.58 98.677,84.58 98.677,85.839
GND on GND (split plane): 84.483,81.786 85.342,81.786 85.342,81.532 84.483,81.532
GND on GND (split plane): 85.342,81.786 86.201,81.786 86.201,81.532 85.342,81.532
GND on GND (split plane): 85.215,81.659 85.215,82.818 85.469,82.818 85.469,81.659
GND on GND (split plane): 85.469,81.659 85.469,80.5 85.215,80.5 85.215,81.659
GND on GND (split plane): 84.483,85.966 85.342,85.966 85.342,85.712 84.483,85.712
GND on GND (split plane): 85.342,85.966 86.201,85.966 86.201,85.712 85.342,85.712
GND on GND (split plane): 85.215,85.839 85.215,87.098 85.469,87.098 85.469,85.839
GND on GND (split plane): 85.469,85.839 85.469,84.58 85.215,84.58 85.215,85.839
GND on GND (split plane): 106.585,81.786 107.444,81.786 107.444,81.532 106.585,81.532
GND on GND (split plane): 107.444,81.786 108.303,81.786 108.303,81.532 107.444,81.532
GND on GND (split plane): 107.317,81.659 107.317,82.818 107.571,82.818 107.571,81.659
GND on GND (split plane): 107.571,81.659 107.571,80.5 107.317,80.5 107.317,81.659
GND on GND (split plane): 93.123,81.786 93.982,81.786 93.982,81.532 93.123,81.532
GND on GND (split plane): 93.982,81.786 94.841,81.786 94.841,81.532 93.982,81.532
GND on GND (split plane): 93.855,81.659 93.855,82.818 94.109,82.818 94.109,81.659
GND on GND (split plane): 94.109,81.659 94.109,80.5 93.855,80.5 93.855,81.659
GND on GND (split plane): 97.945,81.786 98.804,81.786 98.804,81.532 97.945,81.532
GND on GND (split plane): 98.804,81.786 99.663,81.786 99.663,81.532 98.804,81.532
GND on GND (split plane): 98.677,81.659 98.677,82.818 98.931,82.818 98.931,81.659
GND on GND (split plane): 98.931,81.659 98.931,80.5 98.677,80.5 98.677,81.659
GND on GND (split plane): 110.613,86.713 110.613,87.772 110.867,87.772 110.867,86.713
GND on GND (split plane): 110.867,86.713 110.867,85.654 110.613,85.654 110.613,86.713
GND on GND (split plane): 110.74,86.84 111.799,86.84 111.799,86.586 110.74,86.586
GND on GND (split plane): 109.681,86.84 110.74,86.84 110.74,86.586 109.681,86.586
GND on GND (split plane): 110.613,84.173 110.613,85.232 110.867,85.232 110.867,84.173
GND on GND (split plane): 110.867,84.173 110.867,83.114 110.613,83.114 110.613,84.173
GND on GND (split plane): 110.74,84.3 111.799,84.3 111.799,84.046 110.74,84.046
GND on GND (split plane): 109.681,84.3 110.74,84.3 110.74,84.046 109.681,84.046
GND on GND (split plane): 81.867,85.232 81.867,84.173 81.613,84.173 81.613,85.232
GND on GND (split plane): 81.613,83.114 81.613,84.173 81.867,84.173 81.867,83.114
GND on GND (split plane): 81.74,84.3 82.799,84.3 82.799,84.046 81.74,84.046
GND on GND (split plane): 80.681,84.3 81.74,84.3 81.74,84.046 80.681,84.046
GND on GND (split plane): 110.613,137.513 110.613,138.572 110.867,138.572 110.867,137.513
GND on GND (split plane): 110.867,137.513 110.867,136.454 110.613,136.454 110.613,137.513
GND on GND (split plane): 110.74,137.64 111.799,137.64 111.799,137.386 110.74,137.386
GND on GND (split plane): 109.681,137.64 110.74,137.64 110.74,137.386 109.681,137.386
GND on GND (split plane): 93.123,85.966 93.982,85.966 93.982,85.712 93.123,85.712
GND on GND (split plane): 93.982,85.966 94.841,85.966 94.841,85.712 93.982,85.712
GND on GND (split plane): 93.855,85.839 93.855,87.098 94.109,87.098 94.109,85.839
GND on GND (split plane): 94.109,85.839 94.109,84.58 93.855,84.58 93.855,85.839
GND on GND (split plane): 106.585,85.966 107.444,85.966 107.444,85.712 106.585,85.712
GND on GND (split plane): 107.444,85.966 108.303,85.966 108.303,85.712 107.444,85.712
GND on GND (split plane): 107.317,85.839 107.317,87.098 107.571,87.098 107.571,85.839
GND on GND (split plane): 107.571,85.839 107.571,84.58 107.317,84.58 107.317,85.839
3V3 on 3V3 (split plane): 81.613,137.513 81.613,138.572 81.867,138.572 81.867,137.513
3V3 on 3V3 (split plane): 81.867,137.513 81.867,136.454 81.613,136.454 81.613,137.513
3V3 on 3V3 (split plane): 81.74,137.64 82.799,137.64 82.799,137.386 81.74,137.386
3V3 on 3V3 (split plane): 80.681,137.64 81.74,137.64 81.74,137.386 80.681,137.386
3V3 on 3V3 (split plane): 81.613,134.973 81.613,136.032 81.867,136.032 81.867,134.973
3V3 on 3V3 (split plane): 81.867,134.973 81.867,133.914 81.613,133.914 81.613,134.973
3V3 on 3V3 (split plane): 81.74,135.1 82.799,135.1 82.799,134.846 81.74,134.846
3V3 on 3V3 (split plane): 80.681,135.1 81.74,135.1 81.74,134.846 80.681,134.846

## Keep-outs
Board Outline Layer:
  lines w0.254 net "": 78.74,79.843 78.74,139.843 cw(c79.74,139.843) 79.74,140.843 86.868,140.716 86.868,134.747 105.537,134.747 105.537,140.843 112.74,140.843 cw(c112.74,139.843) 113.74,139.843 113.74,79.843 cw(c112.74,79.843) 112.74,78.843 79.74,78.843 cw(c79.74,79.843) 78.74,79.843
